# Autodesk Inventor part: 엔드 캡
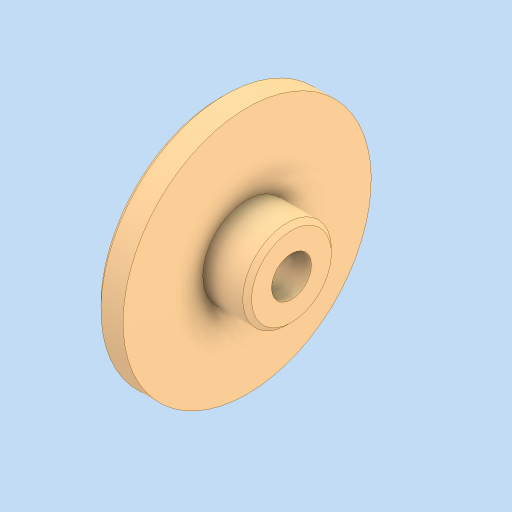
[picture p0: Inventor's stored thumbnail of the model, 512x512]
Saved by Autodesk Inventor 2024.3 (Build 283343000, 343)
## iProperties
Created: 2025-11
Part Number: 엔드 캡
Material: 강철, 연강
Document SubType Name: Modeling
Designer: PC2-03
Density: 7.85 g/cm^3
Appearance: 기본값
Author: jhkim
Sending System: Autodesk Inventor 2026
Preprocessor: ST-DEVELOPER v20.1
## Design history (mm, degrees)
feature "솔리드1"
node "솔리드2"
